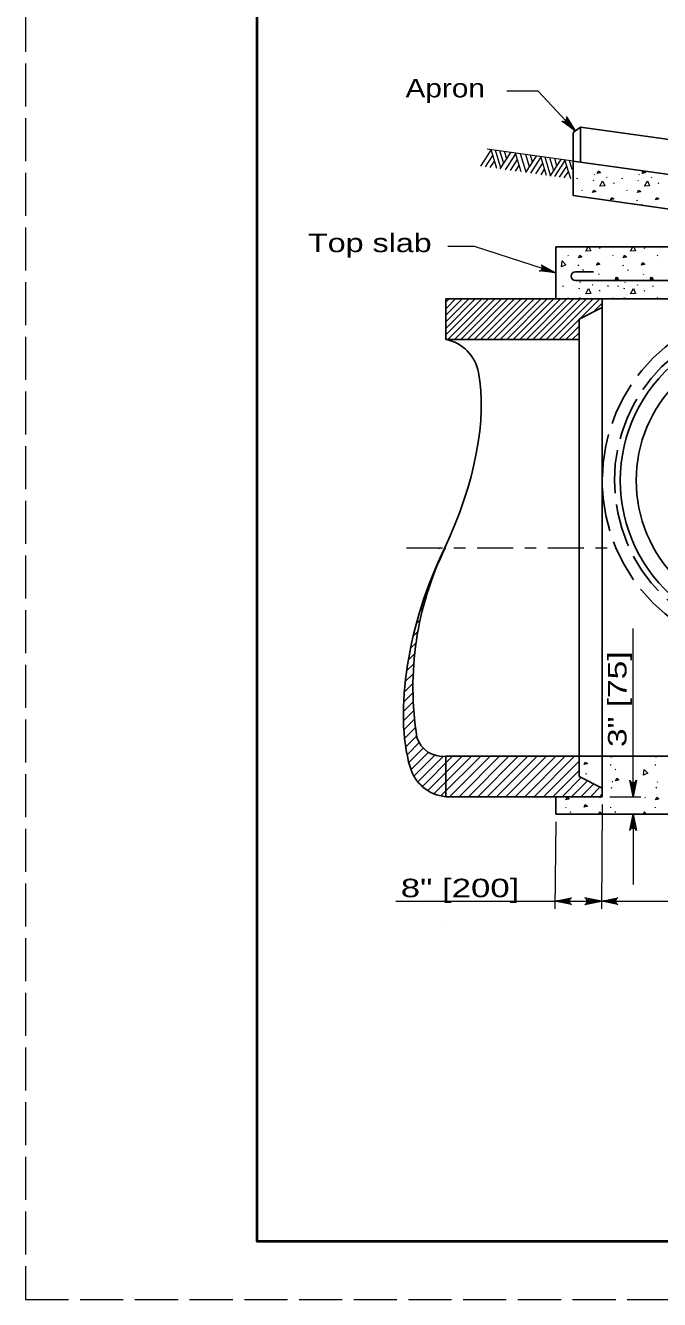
# Model space of a CAD drawing. Extents: x 1073.4 to 1107.4, y 719.4 to 741.4.
# Drawn here: x 1073.36 to 1078.83, y 719.35 to 730.35 of the extents above; entities that cross this region are included whole.
import ezdxf

# ---------------------------------------------------------------- set-up
doc = ezdxf.new("R2010")
doc.units = 0
doc.header["$LTSCALE"] = 0.062
doc.linetypes.add('DOT_DASHED', pattern=[7.7, 5, -1.2, 0.3, -1.2])
doc.linetypes.add('LONG_DASHED', pattern=[7.5, 6, -1.5])
doc.layers.add('1', color=7, linetype='Continuous', lineweight=13)

msp = doc.modelspace()

# ---------------------------------------------------------------- linework, layer by layer
at = {"layer": '1', "lineweight": 25}
for p, q in [((1075.36142, 720.04675), (1075.36142, 740.85408)), ((1078.0865, 729.42867), (1078.149, 729.47683)), ((1078.0865, 729.42867), (1078.0865, 728.88592)), ((1080.51042, 729.14492), (1078.149, 729.47683)), ((1078.149, 729.47683), (1078.149, 729.17408)), ((1080.51042, 728.84217), (1078.0865, 729.18283)), ((1080.51042, 728.54525), (1078.0865, 728.88592)), ((1077.93658, 728.4425), (1078.98608, 728.4425)), ((1077.93658, 727.99275), (1077.93658, 728.4425)), ((1078.10517, 728.22683), (1078.2615, 728.22683)), ((1078.10517, 728.15183), (1078.98483, 728.15183)), ((1077.93658, 727.99275), (1078.98608, 727.99275)), ((1078.33642, 727.99275), (1078.33642, 727.91783)), ((1078.1365, 727.81783), (1078.33642, 727.91783)), ((1078.33642, 727.91783), (1078.33642, 724.04508)), ((1078.1365, 727.81783), (1078.1365, 725.844)), ((1078.1365, 724.04508), (1078.1365, 725.844)), ((1076.98708, 724.04508), (1078.1365, 724.04508)), ((1076.98708, 723.69525), (1076.98708, 724.04508)), ((1078.33642, 723.69525), (1076.98708, 723.69525)), ((1077.93658, 723.54533), (1077.93658, 723.69525)), ((1077.93658, 723.54533), (1081.73483, 723.54533))]:
    msp.add_line(p, q, dxfattribs=at)
at = {"layer": '1'}
for p, q in [((1077.78325, 729.78675), (1077.51408, 729.78675)), ((1078.10492, 729.44275), (1077.78325, 729.78675)), ((1078.00425, 729.52417), (1078.10492, 729.44275)), ((1078.01375, 729.52708), (1078.10492, 729.44275)), ((1078.02125, 729.53233), (1078.10492, 729.44275)), ((1078.02808, 729.54183), (1078.10492, 729.44275)), ((1078.03075, 729.55108), (1078.10492, 729.44275)), ((1077.289, 729.13875), (1077.37842, 729.2775)), ((1077.33092, 729.13275), (1077.39308, 729.23017)), ((1078.0865, 729.18283), (1077.34417, 729.28717)), ((1077.42708, 729.11925), (1077.37775, 729.28242)), ((1077.43858, 729.20108), (1077.41575, 729.27708)), ((1077.46208, 729.12408), (1077.43858, 729.20108)), ((1077.48683, 729.16233), (1077.45333, 729.27183)), ((1077.4565, 729.11508), (1077.54892, 729.25842)), ((1077.51358, 729.20367), (1077.49517, 729.26592)), ((1077.50217, 729.10875), (1077.59075, 729.24517)), ((1077.54592, 729.10258), (1077.60608, 729.19558)), ((1077.63817, 729.08958), (1077.58842, 729.25283)), ((1077.68075, 729.088), (1077.63267, 729.24658)), ((1077.70933, 729.1325), (1077.67692, 729.24042)), ((1077.67817, 729.084), (1077.77058, 729.22708)), ((1077.7355, 729.17442), (1077.71775, 729.23467)), ((1077.72058, 729.07808), (1077.80858, 729.21408)), ((1077.85667, 729.05892), (1077.80633, 729.22217)), ((1077.892, 729.05875), (1077.84383, 729.21692)), ((1077.91875, 729.10008), (1077.88542, 729.21108)), ((1077.889, 729.05442), (1077.98142, 729.19808)), ((1077.94658, 729.14333), (1077.92808, 729.20508)), ((1078.065, 729.02967), (1078.01558, 729.19283)), ((1077.37133, 729.12708), (1077.40742, 729.18375)), ((1077.58925, 729.0965), (1077.621, 729.14592)), ((1077.76433, 729.07192), (1077.82392, 729.16483)), ((1077.809, 729.06558), (1077.83958, 729.11375)), ((1077.927, 729.04908), (1078.01642, 729.18783)), ((1077.96892, 729.04308), (1078.03108, 729.14067)), ((1078.00942, 729.03742), (1078.04542, 729.094)), ((1078.07642, 729.11142), (1078.05367, 729.18742)), ((1078.13508, 729.1755), (1078.13517, 729.176)), ((1078.42708, 729.133), (1078.428, 729.13483)), ((1078.68058, 729.07625), (1078.691, 729.09783)), ((1078.12133, 729.03008), (1078.12483, 729.03808)), ((1078.25975, 729.0115), (1078.26333, 729.0195)), ((1078.2665, 729.07008), (1078.27008, 729.06475)), ((1078.37283, 729.04742), (1078.37642, 729.04208)), ((1078.436, 728.99108), (1078.43958, 728.99908)), ((1078.50783, 729.03008), (1078.51142, 729.03808)), ((1078.64633, 729.0115), (1078.64992, 729.0195)), ((1078.65308, 729.07008), (1078.65667, 729.06475)), ((1078.75942, 729.04742), (1078.763, 729.04208)), ((1078.82258, 728.99108), (1078.82608, 728.99908)), ((1078.16042, 728.93433), (1078.16392, 728.929)), ((1078.547, 728.93433), (1078.5505, 728.929)), ((1078.63667, 728.84908), (1078.6375, 728.84125)), ((1078.67908, 728.80267), (1078.68233, 728.81008)), ((1077.23575, 728.44675), (1077.00383, 728.44675)), ((1077.93658, 728.21767), (1077.23575, 728.44675)), ((1078.19475, 728.40442), (1078.21492, 728.4425)), ((1078.31458, 728.42842), (1078.31817, 728.43642)), ((1078.58142, 728.40442), (1078.6015, 728.4425)), ((1078.70117, 728.42842), (1078.70475, 728.43642)), ((1078.039, 728.37167), (1078.0425, 728.36633)), ((1078.4255, 728.37167), (1078.42908, 728.36633)), ((1078.81208, 728.37167), (1078.81567, 728.36633)), ((1077.80917, 728.24042), (1077.93658, 728.21767)), ((1077.81608, 728.2475), (1077.93658, 728.21767)), ((1077.81942, 728.27675), (1077.93658, 728.21767)), ((1077.82008, 728.25575), (1077.93658, 728.21767)), ((1077.82158, 728.26742), (1077.93658, 728.21767)), ((1078.12867, 728.28642), (1078.12958, 728.2785)), ((1078.17083, 728.23942), (1078.17442, 728.24742)), ((1078.30575, 728.203), (1078.30925, 728.211)), ((1078.51525, 728.28642), (1078.51608, 728.2785)), ((1078.55742, 728.23942), (1078.56092, 728.24742)), ((1078.69233, 728.203), (1078.69583, 728.211)), ((1077.99992, 728.10008), (1078.00342, 728.10808)), ((1078.14508, 728.14008), (1078.14867, 728.13475)), ((1078.25142, 728.11742), (1078.255, 728.11208)), ((1078.38642, 728.10008), (1078.39008, 728.10808)), ((1078.47325, 728.10008), (1078.47675, 728.10808)), ((1078.53167, 728.14008), (1078.53525, 728.13475)), ((1078.638, 728.11742), (1078.6415, 728.11208)), ((1078.77308, 728.10008), (1078.77658, 728.10808)), ((1076.98708, 727.96475), (1077.01508, 727.99275)), ((1076.98708, 727.90825), (1077.07158, 727.99275)), ((1076.98708, 727.85167), (1077.12817, 727.99275)), ((1076.98708, 727.79517), (1077.18475, 727.99275)), ((1076.98708, 727.73858), (1077.24125, 727.99275)), ((1076.98708, 727.68208), (1077.29775, 727.99275)), ((1077.0045, 727.643), (1077.35433, 727.99275)), ((1077.06108, 727.643), (1077.41083, 727.99275)), ((1077.11758, 727.643), (1077.46742, 727.99275)), ((1077.17408, 727.643), (1077.52392, 727.99275)), ((1077.23067, 727.643), (1077.5805, 727.99275)), ((1077.28717, 727.643), (1077.637, 727.99275)), ((1077.34375, 727.643), (1077.69358, 727.99275)), ((1077.40025, 727.643), (1077.75008, 727.99275)), ((1077.45683, 727.643), (1077.80667, 727.99275)), ((1077.51333, 727.643), (1077.86317, 727.99275)), ((1077.56992, 727.643), (1077.91975, 727.99275)), ((1077.62642, 727.643), (1077.97625, 727.99275)), ((1077.683, 727.643), (1078.03283, 727.99275)), ((1077.73958, 727.643), (1078.08942, 727.99275)), ((1077.79608, 727.643), (1078.14592, 727.99275)), ((1077.85267, 727.643), (1078.20242, 727.99275)), ((1077.90917, 727.643), (1078.259, 727.99275)), ((1077.96575, 727.643), (1078.31558, 727.99275)), ((1078.039, 728.00433), (1078.0425, 727.999)), ((1078.13842, 728.0815), (1078.14192, 728.0895)), ((1078.31458, 728.06108), (1078.31817, 728.06908)), ((1078.4255, 728.00433), (1078.42908, 727.999)), ((1078.52492, 728.0815), (1078.5285, 728.0895)), ((1078.70117, 728.06108), (1078.70475, 728.06908)), ((1078.81208, 728.00433), (1078.81567, 727.999)), ((1078.25775, 727.8785), (1078.33642, 727.95708)), ((1078.02225, 727.643), (1078.1365, 727.75725)), ((1078.07875, 727.643), (1078.1365, 727.70067)), ((1078.13533, 727.643), (1078.1365, 727.64417)), ((1076.92608, 725.83617), (1076.93258, 725.84258)), ((1076.85133, 725.54975), (1076.86408, 725.56267)), ((1076.80533, 725.42283), (1076.82342, 725.441)), ((1076.76633, 725.30292), (1076.79133, 725.32792)), ((1076.70633, 725.08108), (1076.74625, 725.121)), ((1076.73392, 725.18958), (1076.76608, 725.22175)), ((1078.603, 723.69525), (1078.603, 725.14792)), ((1076.68317, 724.977), (1076.73108, 725.02483)), ((1076.66442, 724.87725), (1076.71967, 724.93242)), ((1076.64942, 724.78133), (1076.7115, 724.84342)), ((1076.63775, 724.68875), (1076.70625, 724.75725)), ((1076.62408, 724.51308), (1076.70467, 724.59375)), ((1076.62942, 724.59933), (1076.70408, 724.67417)), ((1076.62167, 724.42975), (1076.70708, 724.51533)), ((1076.62217, 724.34942), (1076.71142, 724.43867)), ((1076.62567, 724.27183), (1076.7185, 724.36475)), ((1076.632, 724.19733), (1076.72692, 724.29217)), ((1076.64125, 724.12567), (1076.73675, 724.22108)), ((1076.6535, 724.057), (1076.75875, 724.16217)), ((1076.66875, 723.99125), (1076.79308, 724.1155)), ((1076.68692, 723.92842), (1076.83742, 724.07892)), ((1076.71275, 723.87333), (1076.89292, 724.0535)), ((1076.74525, 723.82492), (1076.96375, 724.04342)), ((1076.78508, 723.78383), (1077.04642, 724.04508)), ((1076.83108, 723.74892), (1077.12733, 724.04508)), ((1076.88458, 723.72142), (1077.20817, 724.04508)), ((1076.94575, 723.70175), (1077.28917, 724.04508)), ((1077.02033, 723.69525), (1077.37008, 724.04508)), ((1077.10125, 723.69525), (1077.45108, 724.04508)), ((1077.18225, 723.69525), (1077.53208, 724.04508)), ((1077.26317, 723.69525), (1077.61308, 724.04508)), ((1077.34408, 723.69525), (1077.69392, 724.04508)), ((1077.42508, 723.69525), (1077.77483, 724.04508)), ((1077.506, 723.69525), (1077.85583, 724.04508)), ((1077.587, 723.69525), (1077.93675, 724.04508)), ((1077.66792, 723.69525), (1078.01775, 724.04508)), ((1077.74883, 723.69525), (1078.09867, 724.04508)), ((1078.41067, 724.03558), (1078.41517, 724.04508)), ((1078.79717, 724.03558), (1078.80175, 724.04508)), ((1077.82975, 723.69525), (1078.1365, 724.00192)), ((1077.91075, 723.69525), (1078.1365, 723.921)), ((1078.40717, 723.97358), (1078.40808, 723.96558)), ((1078.44933, 723.92642), (1078.45283, 723.93442)), ((1078.79375, 723.97358), (1078.79467, 723.96558)), ((1077.99175, 723.69525), (1078.15658, 723.86008)), ((1078.07267, 723.69525), (1078.2105, 723.83308)), ((1078.15358, 723.69525), (1078.2645, 723.80617)), ((1078.191, 723.843), (1078.19108, 723.84292)), ((1078.19767, 723.89), (1078.20108, 723.898)), ((1078.42358, 723.82708), (1078.42708, 723.82175)), ((1078.58508, 723.82342), (1078.603, 723.69525)), ((1078.59392, 723.81908), (1078.603, 723.69525)), ((1078.62275, 723.825), (1078.603, 723.69525)), ((1078.61442, 723.82008), (1078.603, 723.69525)), ((1078.603, 723.81775), (1078.603, 723.69525)), ((1078.81017, 723.82708), (1078.81375, 723.82175)), ((1077.93658, 723.69525), (1077.93658, 723.62033)), ((1078.2345, 723.69525), (1078.3185, 723.77917)), ((1078.3155, 723.69525), (1078.33642, 723.71617)), ((1078.31742, 723.69133), (1078.321, 723.68608)), ((1078.40308, 723.69525), (1078.66958, 723.69525)), ((1078.41683, 723.7685), (1078.42042, 723.7765)), ((1078.70408, 723.69133), (1078.70758, 723.68608)), ((1078.80342, 723.7685), (1078.807, 723.7765)), ((1078.02058, 723.60625), (1078.0215, 723.59825)), ((1078.33642, 723.62867), (1078.32917, 722.72683)), ((1078.40717, 723.60625), (1078.40808, 723.59825)), ((1078.79375, 723.60625), (1078.79467, 723.59825)), ((1077.93658, 723.47875), (1077.92942, 722.72683)), ((1077.93658, 723.55342), (1077.94442, 723.54533)), ((1078.98608, 723.54533), (1077.93658, 723.54533)), ((1078.06267, 723.55908), (1078.06625, 723.56708)), ((1078.44933, 723.55908), (1078.45283, 723.56708)), ((1078.58308, 723.41567), (1078.603, 723.54533)), ((1078.59142, 723.4205), (1078.603, 723.54533)), ((1078.603, 723.42275), (1078.603, 723.54533)), ((1078.61208, 723.4215), (1078.603, 723.54533)), ((1078.62092, 723.41708), (1078.603, 723.54533)), ((1078.603, 723.54533), (1078.603, 722.93675)), ((1078.05758, 722.8115), (1077.92942, 722.7935)), ((1078.201, 722.8115), (1078.32917, 722.7935)), ((1078.45742, 722.8115), (1078.32917, 722.7935)), ((1078.05317, 722.80258), (1077.92942, 722.7935)), ((1078.05192, 722.7935), (1077.92942, 722.7935)), ((1078.05417, 722.782), (1077.92942, 722.7935)), ((1078.05908, 722.77367), (1077.92942, 722.7935)), ((1078.19942, 722.77367), (1078.32917, 722.7935)), ((1078.20442, 722.782), (1078.32917, 722.7935)), ((1078.20533, 722.80258), (1078.32917, 722.7935)), ((1078.20667, 722.7935), (1078.32917, 722.7935)), ((1078.45308, 722.80258), (1078.32917, 722.7935)), ((1078.45175, 722.7935), (1078.32917, 722.7935)), ((1078.454, 722.782), (1078.32917, 722.7935)), ((1078.45883, 722.77367), (1078.32917, 722.7935))]:
    msp.add_line(p, q, dxfattribs=at)
at = {"layer": '1', "linetype": 'DOT_DASHED'}
msp.add_line((1076.64808, 725.844), (1078.40742, 725.844), dxfattribs=at)
at = {"layer": '1', "linetype": 'LONG_DASHED', "lineweight": 25}
msp.add_line((1078.33642, 723.77017), (1078.33642, 724.04508), dxfattribs=at)
at = {"layer": '1', "linetype": 'LONG_DASHED'}
msp.add_lwpolyline([(1073.36142, 719.35408), (1107.36142, 719.35408), (1107.36142, 741.35408), (1073.36142, 741.35408)], close=True, dxfattribs=at)
at = {"layer": '1', "lineweight": 25}
for points in [[(1106.86142, 719.85408), (1075.36142, 719.85408), (1075.36142, 740.85408)], [(1078.1365, 727.643), (1076.98708, 727.643), (1076.98708, 727.99275), (1078.33642, 727.99275)], [(1078.98608, 723.54533), (1078.98608, 724.04508), (1078.1365, 724.04508), (1078.1365, 723.87017)], [(1078.1365, 723.87017), (1078.33642, 723.77017), (1078.33642, 723.69525)]]:
    msp.add_lwpolyline(points, dxfattribs=at)
at = {"layer": '1', "lineweight": 40}
msp.add_lwpolyline([(1075.36142, 740.85408), (1106.86142, 740.85408), (1106.86142, 719.85408), (1075.36142, 719.85408)], close=True, dxfattribs=at)
msp.add_lwpolyline([(1075.36142, 740.85408), (1106.86142, 740.85408), (1106.86142, 719.85408), (1075.36142, 719.85408)], close=True, dxfattribs=at)
at = {"layer": '1'}
for points in [[(1078.02892, 729.56558), (1078.10492, 729.44275), (1077.9875, 729.52683)], [(1078.69217, 729.09767), (1078.709, 729.08508), (1078.68058, 729.07625)], [(1078.31617, 728.96708), (1078.34008, 729.01242), (1078.35875, 728.97067), (1078.31708, 728.96708)], [(1078.70275, 728.96708), (1078.72675, 729.01242), (1078.74542, 728.97067), (1078.70367, 728.96708)], [(1078.22192, 728.4425), (1078.23742, 728.408), (1078.19558, 728.40442)], [(1078.6085, 728.4425), (1078.624, 728.408), (1078.58225, 728.40442)], [(1077.9845, 728.27033), (1077.99158, 728.32108), (1078.02342, 728.28817), (1077.98542, 728.27058)], [(1077.81075, 728.28858), (1077.93658, 728.21767), (1077.79317, 728.23475)], [(1078.02317, 727.99275), (1078.04142, 727.995), (1078.04525, 727.99275)], [(1078.13767, 727.99275), (1078.14275, 728.00342), (1078.15708, 727.99275)], [(1078.19475, 728.03717), (1078.21875, 728.08242), (1078.23742, 728.04075), (1078.19558, 728.03717)], [(1078.52425, 727.99275), (1078.52942, 728.00342), (1078.54358, 727.99275)], [(1078.58142, 728.03717), (1078.60533, 728.08242), (1078.624, 728.04075), (1078.58225, 728.03717)], [(1078.43825, 724.04508), (1078.43908, 724.04442), (1078.41067, 724.03558)], [(1078.82483, 724.04508), (1078.82567, 724.04442), (1078.79717, 724.03558)], [(1078.69217, 723.88083), (1078.69925, 723.93158), (1078.73108, 723.89875), (1078.69308, 723.88108)], [(1078.63125, 723.83683), (1078.603, 723.69525), (1078.57467, 723.83683)], [(1078.31008, 723.54533), (1078.31267, 723.56425), (1078.331, 723.54533)], [(1078.57467, 723.40375), (1078.603, 723.54533), (1078.63125, 723.40375)], [(1078.69658, 723.54533), (1078.69925, 723.56425), (1078.71758, 723.54533)], [(1078.071, 722.76517), (1077.92942, 722.7935), (1078.071, 722.82183)], [(1078.18758, 722.76517), (1078.32917, 722.7935), (1078.18758, 722.82183)], [(1078.47075, 722.76517), (1078.32917, 722.7935), (1078.47075, 722.82183)], [(1076.55733, 722.7935), (1078.32917, 722.7935), (1081.31533, 722.7935), (1083.12442, 722.7935)]]:
    msp.add_lwpolyline(points, dxfattribs=at)
for points in [[(1078.294, 729.07625), (1078.30467, 729.09842), (1078.32242, 729.08508)], [(1078.25358, 728.91125), (1078.26417, 728.93342), (1078.282, 728.92008)], [(1078.40958, 728.84783), (1078.42017, 728.87), (1078.438, 728.85667)], [(1078.64008, 728.91125), (1078.65075, 728.93342), (1078.6685, 728.92008)], [(1078.79608, 728.84783), (1078.80675, 728.87), (1078.8245, 728.85667)], [(1078.13208, 728.34858), (1078.14275, 728.37075), (1078.16058, 728.35742)], [(1078.51875, 728.34858), (1078.52942, 728.37075), (1078.54708, 728.35742)], [(1078.28808, 728.28508), (1078.29875, 728.30733), (1078.31658, 728.294)], [(1078.67475, 728.28508), (1078.68542, 728.30733), (1078.70308, 728.294)], [(1078.18008, 723.97217), (1078.19075, 723.99433), (1078.20842, 723.98108)], [(1078.45108, 723.83325), (1078.46175, 723.85542), (1078.4795, 723.84208)], [(1078.02408, 723.66825), (1078.03475, 723.69042), (1078.05242, 723.67708)], [(1078.79717, 723.66825), (1078.80783, 723.69042), (1078.82567, 723.67708)], [(1078.18008, 723.60483), (1078.19075, 723.62708), (1078.20842, 723.61375)]]:
    msp.add_lwpolyline(points, close=True, dxfattribs=at)
for centre, start, end in [((1078.00037, 729.55456), 245.17211, 20.99823), ((1077.79113, 728.26516), 273.98886, 49.81499), ((1078.60293, 723.84829), 202.08782, 337.91395), ((1078.60299, 723.3923), 22.08782, 157.91395), ((1078.0824, 722.79356), 112.08782, 247.91395), ((1078.17614, 722.79356), 292.08605, 67.91218), ((1078.48221, 722.79356), 112.08782, 247.91395)]:
    msp.add_arc(centre, 0.03056, start, end, dxfattribs=at)
at = {"layer": '1', "lineweight": 25}
for centre, major_axis, ratio, start_param, end_param in [((1078.10519, 728.18933), (0.03752, 0), 0.999895, 1.57079633, 4.71238898), ((1076.92081, 727.29457), (0.35468, 0), 0.999895, 0.18136545, 1.38293209), ((1079.82951, 726.42488), (1.33687, 0), 0.999895, 2.25348521, 4.02970005), ((1076.31606, 726.23295), (-0.68431, -1.53841), 0.45423, 1.52025823, 2.56990846), ((1079.82951, 726.42488), (1.19944, 0), 0.999895, 2.35065535, 3.93252996), ((1077.52404, 725.16154), (0.53831, 1.59536), 0.454237, 1.28629854, 2.56990022), ((1079.42502, 724.64333), (-2.72136, 0), 0.999895, 5.82640908, 6.44414922), ((1076.96115, 724.27573), (-0.23265, 0), 0.999895, 0.29892414, 1.68267639), ((1077.02062, 724.04831), (-0.35468, 0), 0.999895, 0.27446112, 1.47602776)]:
    msp.add_ellipse(centre, major_axis=major_axis, ratio=ratio, start_param=start_param, end_param=end_param, dxfattribs=at)
at = {"layer": '1'}
for centre, major_axis, start_param, end_param in [((1078.46263, 728.16548), (0.01369, 0), 1.89150989, 7.96833716), ((1078.46263, 728.16548), (0.01192, 0), 1.89150853, 7.96833595), ((1078.46263, 728.16548), (0.00893, 0), 1.89150499, 7.96833284), ((1078.46263, 728.16548), (0.00724, 0), 1.89150169, 7.96832993), ((1078.46263, 728.16548), (0.00477, 0), 1.89149263, 7.96832198), ((1078.46263, 728.16548), (0.00188, 0), 1.89145185, 7.9682863), ((1078.76248, 728.16548), (0.01369, 0), 1.89150989, 7.96833716), ((1078.76248, 728.16548), (0.01192, 0), 1.89150853, 7.96833595), ((1078.76248, 728.16548), (0.00893, 0), 1.89150499, 7.96833284), ((1078.76248, 728.16548), (0.00724, 0), 1.89150169, 7.96832993), ((1078.76248, 728.16548), (0.00477, 0), 1.89149263, 7.96832198), ((1078.76248, 728.16548), (0.00188, 0), 1.89145185, 7.9682863), ((1076.9227, 722.96367), (0.35468, 0), 4.81062091, 4.81062096)]:
    msp.add_ellipse(centre, major_axis=major_axis, ratio=0.999895, start_param=start_param, end_param=end_param, dxfattribs=at)
at = {"layer": '1', "linetype": 'LONG_DASHED', "lineweight": 25}
for centre, major_axis in [((1079.82948, 726.42488), (1.49306, 0)), ((1079.82951, 726.42488), (1.38685, 0))]:
    msp.add_ellipse(centre, major_axis=major_axis, ratio=0.999895, dxfattribs=at)

# ---------------------------------------------------------------- texts
at = {"layer": '1'}
for s, width, p in [('Apron', 1.2, (1076.63975, 729.73325)), ('Top slab', 1.3, (1075.79883, 728.397)), ('8" [200]', 1.4, (1076.599, 722.82725))]:
    msp.add_text(s, height=0.16, dxfattribs=dict(at, width=width)).set_placement(p)
at = {"layer": '1', "width": 1.35}
msp.add_text('3" [75]', height=0.16, rotation=90, dxfattribs=at).set_placement((1078.54642, 724.12458))

doc.saveas('drawing.dxf')
